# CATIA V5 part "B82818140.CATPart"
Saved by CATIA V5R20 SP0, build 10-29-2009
Part number: B82818140
Revision: 5
Definition: design
Nomenclature: B82818140
Source: made
Description: NOT SPECIFIED
Bounding box of the stored display mesh (mm): x -10.833 to 10.833, y -11 to 11, z 0 to 140
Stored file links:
  C:\Users\Raffaele\Desktop\3D X SITO CF\BOLEX\7-PILLAR REF 828\B82818140.CATPart
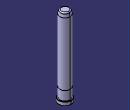
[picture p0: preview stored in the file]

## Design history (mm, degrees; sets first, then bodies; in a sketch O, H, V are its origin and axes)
Body1 "MANIFOLD_SOLID_BREP #450" (main body)
  Solid1: solid without history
